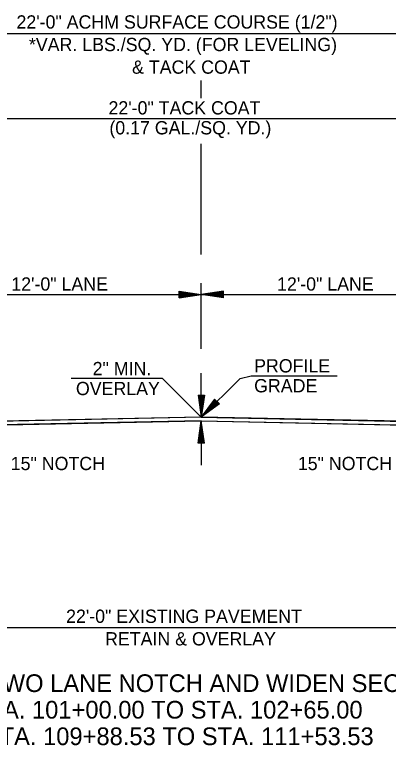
# Model space of a CAD drawing. Extents: x 1371763 to 1372860, y 385599 to 385872.
# Drawn here: x 1372352.15 to 1372369.02, y 385654.16 to 385687.19 of the extents above; entities that cross this region are included whole.
import ezdxf

# ---------------------------------------------------------------- set-up
doc = ezdxf.new("R2010")
doc.units = 0
doc.layers.add('R_Draft', color=7, linetype='Continuous')

msp = doc.modelspace()

# ---------------------------------------------------------------- linework, layer by layer
at = {"layer": 'R_Draft'}
for p, q in [((1372349.579, 385686.33), (1372371.579, 385686.33)), ((1372360.576, 385683.405), (1372360.576, 385684.215)), ((1372349.579, 385682.485), (1372371.579, 385682.485)), ((1372360.577, 385676.344), (1372360.576, 385681.341)), ((1372360.577, 385672.074), (1372360.578, 385675.048)), ((1372348.578, 385674.541), (1372360.578, 385674.541)), ((1372359.578, 385674.691), (1372360.578, 385674.541)), ((1372359.578, 385674.391), (1372359.578, 385674.691)), ((1372359.578, 385674.666), (1372360.411, 385674.541)), ((1372359.578, 385674.64), (1372360.239, 385674.541)), ((1372359.578, 385674.615), (1372360.072, 385674.541)), ((1372359.578, 385674.59), (1372359.903, 385674.541)), ((1372359.578, 385674.564), (1372359.736, 385674.541)), ((1372359.578, 385674.391), (1372360.578, 385674.541)), ((1372359.578, 385674.492), (1372359.903, 385674.541)), ((1372359.578, 385674.441), (1372360.239, 385674.541)), ((1372359.578, 385674.416), (1372360.411, 385674.541)), ((1372359.578, 385674.466), (1372360.072, 385674.541)), ((1372359.578, 385674.517), (1372359.736, 385674.541)), ((1372361.578, 385674.691), (1372360.578, 385674.541)), ((1372360.578, 385674.541), (1372372.578, 385674.541)), ((1372361.578, 385674.391), (1372360.578, 385674.541)), ((1372361.578, 385674.666), (1372360.745, 385674.541)), ((1372361.578, 385674.416), (1372360.745, 385674.541)), ((1372361.578, 385674.64), (1372360.917, 385674.541)), ((1372361.578, 385674.441), (1372360.917, 385674.541)), ((1372361.578, 385674.615), (1372361.083, 385674.541)), ((1372361.578, 385674.466), (1372361.083, 385674.541)), ((1372361.578, 385674.59), (1372361.253, 385674.541)), ((1372361.578, 385674.492), (1372361.253, 385674.541)), ((1372361.578, 385674.564), (1372361.42, 385674.541)), ((1372361.578, 385674.517), (1372361.42, 385674.541)), ((1372361.578, 385674.391), (1372361.578, 385674.691)), ((1372358.829, 385670.739), (1372354.703, 385670.739)), ((1372360.579, 385668.989), (1372358.829, 385670.739)), ((1372360.579, 385668.989), (1372360.579, 385670.989)), ((1372360.579, 385668.989), (1372362.329, 385670.739)), ((1372362.329, 385670.739), (1372362.829, 385670.864)), ((1372362.829, 385670.864), (1372366.715, 385670.864)), ((1372360.429, 385669.989), (1372360.579, 385668.989)), ((1372360.429, 385669.989), (1372360.729, 385669.989)), ((1372360.454, 385669.989), (1372360.579, 385669.156)), ((1372360.48, 385669.989), (1372360.579, 385669.328)), ((1372360.505, 385669.989), (1372360.579, 385669.495)), ((1372360.531, 385669.989), (1372360.579, 385669.664)), ((1372360.556, 385669.989), (1372360.579, 385669.831)), ((1372360.729, 385669.989), (1372360.579, 385668.989)), ((1372360.628, 385669.989), (1372360.579, 385669.664)), ((1372360.679, 385669.989), (1372360.579, 385669.328)), ((1372360.704, 385669.989), (1372360.579, 385669.156)), ((1372360.654, 385669.989), (1372360.579, 385669.495)), ((1372360.603, 385669.989), (1372360.579, 385669.831)), ((1372361.18, 385669.803), (1372360.579, 385668.989)), ((1372361.198, 385669.785), (1372360.697, 385669.108)), ((1372361.216, 385669.767), (1372360.819, 385669.229)), ((1372361.234, 385669.749), (1372360.937, 385669.347)), ((1372361.393, 385669.59), (1372361.18, 385669.803)), ((1372361.393, 385669.59), (1372360.579, 385668.989)), ((1372361.375, 385669.608), (1372360.697, 385669.108)), ((1372361.357, 385669.626), (1372360.819, 385669.229)), ((1372361.339, 385669.644), (1372360.937, 385669.347)), ((1372361.252, 385669.731), (1372361.057, 385669.467)), ((1372361.321, 385669.662), (1372361.057, 385669.467)), ((1372361.27, 385669.713), (1372361.175, 385669.585)), ((1372361.303, 385669.68), (1372361.175, 385669.585)), ((1372360.579, 385668.989), (1372348.577, 385668.749)), ((1372360.429, 385667.823), (1372360.579, 385668.823)), ((1372360.579, 385668.989), (1372372.577, 385668.749)), ((1372360.579, 385668.823), (1372372.661, 385668.581)), ((1372360.729, 385667.823), (1372360.579, 385668.823)), ((1372360.579, 385668.823), (1372360.579, 385666.823)), ((1372360.454, 385667.823), (1372360.579, 385668.656)), ((1372360.48, 385667.823), (1372360.579, 385668.484)), ((1372360.704, 385667.823), (1372360.579, 385668.656)), ((1372360.679, 385667.823), (1372360.579, 385668.484)), ((1372360.505, 385667.823), (1372360.579, 385668.317)), ((1372360.53, 385667.823), (1372360.579, 385668.148)), ((1372360.654, 385667.823), (1372360.579, 385668.317)), ((1372360.628, 385667.823), (1372360.579, 385668.148)), ((1372360.729, 385667.823), (1372360.429, 385667.823)), ((1372360.556, 385667.823), (1372360.579, 385667.981)), ((1372360.603, 385667.823), (1372360.579, 385667.981)), ((1372349.579, 385659.487), (1372371.579, 385659.487))]:
    msp.add_line(p, q, dxfattribs=at)
msp.add_lwpolyline([(1372360.579, 385668.989), (1372348.577, 385668.749), (1372346.58, 385668.67), (1372340.576, 385668.429), (1372340.576, 385668.264), (1372346.478, 385668.5), (1372348.493, 385668.581), (1372349.58, 385668.603), (1372360.579, 385668.823), (1372371.578, 385668.603), (1372372.661, 385668.581), (1372374.682, 385668.5), (1372380.577, 385668.265), (1372380.577, 385668.43), (1372374.597, 385668.669), (1372372.577, 385668.749)], close=True, dxfattribs=at)
msp.add_lwpolyline([(1372360.579, 385668.823), (1372348.493, 385668.581), (1372340.576, 385668.264)], dxfattribs=at)

# ---------------------------------------------------------------- texts
for s, p in [('22\'-0" ACHM SURFACE COURSE (1/2")', (1372352.233, 385686.554)), ('*VAR. LBS./SQ. YD. (FOR LEVELING)', (1372352.795, 385685.534)), ('& TACK COAT', (1372357.451, 385684.514)), ('22\'-0" TACK COAT', (1372356.388, 385682.672)), ('(0.17 GAL./SQ. YD.)', (1372356.428, 385681.772)), ('12\'-0" LANE', (1372352, 385674.712)), ('12\'-0" LANE', (1372364, 385674.712)), ('22\'-0" EXISTING PAVEMENT', (1372354.473, 385659.697)), ('RETAIN & OVERLAY', (1372356.233, 385658.677))]:
    msp.add_text(s, height=0.6, rotation=360, dxfattribs=at).set_placement(p)
for s, height, p in [('2" MIN.', 0.6, (1372355.672, 385670.889)), ('PROFILE', 0.6, (1372362.963, 385671.014)), ('OVERLAY', 0.6, (1372354.917, 385669.989)), ('GRADE', 0.6, (1372362.963, 385670.114)), ('15" NOTCH', 0.6, (1372351.975, 385666.6)), ('15" NOTCH', 0.6, (1372364.937, 385666.6)), ('HWY. 72 - TWO LANE NOTCH AND WIDEN SECTION', 0.8, (1372345.729, 385656.572)), ('STA. 101+00.00 TO STA. 102+65.00', 0.8, (1372350.258, 385655.372)), ('STA. 109+88.53 TO STA. 111+53.53', 0.8, (1372350.759, 385654.172))]:
    msp.add_text(s, height=height, dxfattribs=at).set_placement(p)

doc.saveas('drawing.dxf')
